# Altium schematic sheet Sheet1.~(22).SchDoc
size A; SheetNumber: 1; SheetTotal: 1
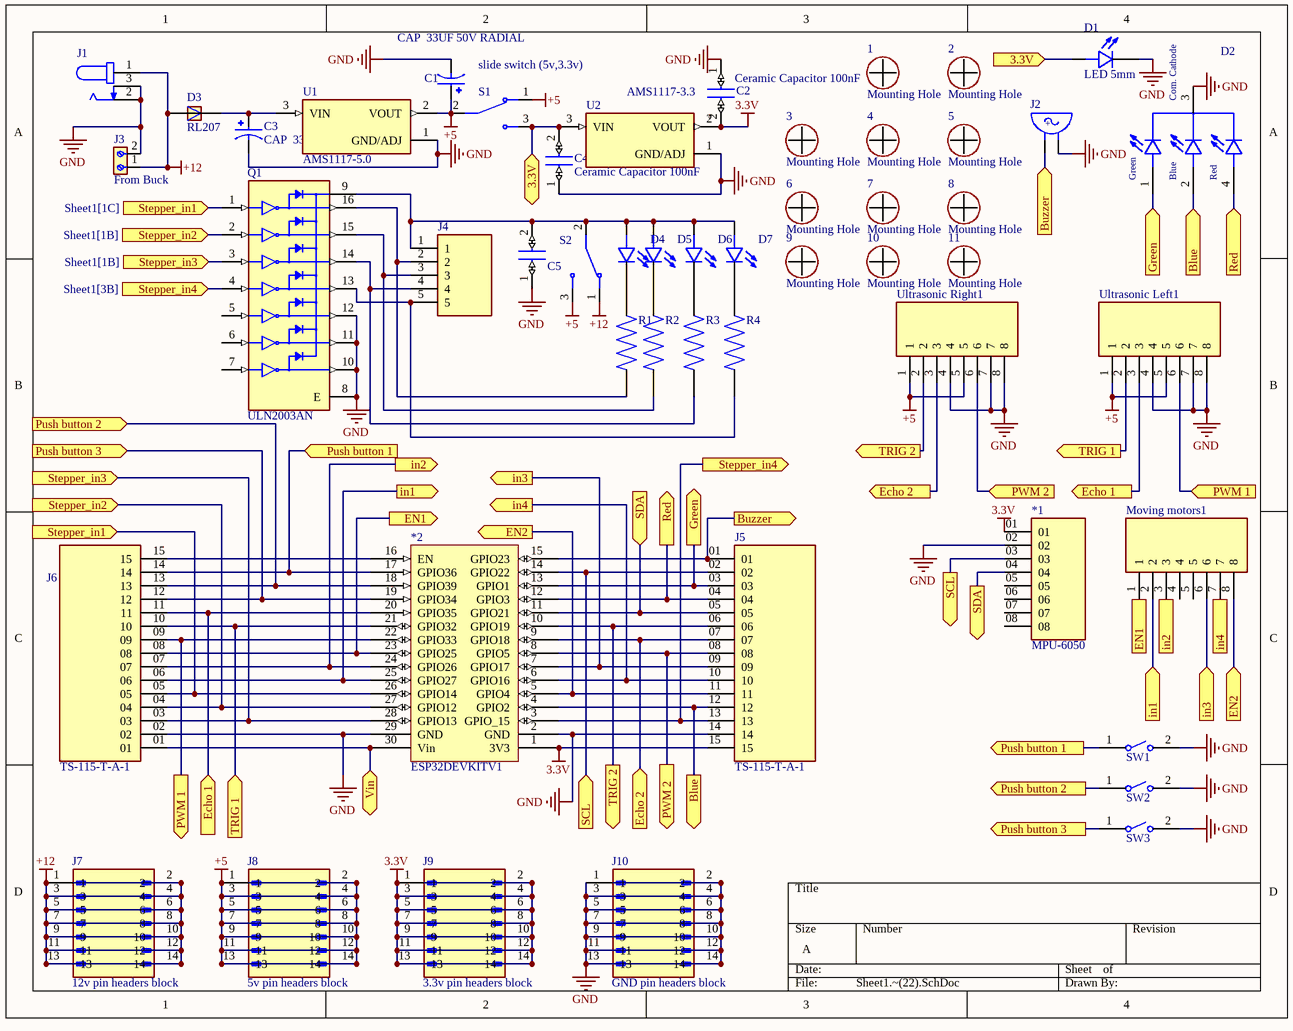
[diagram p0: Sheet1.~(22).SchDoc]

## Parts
1  Mounting Hole  [PCBComponent_1]
2  Mounting Hole  [PCBComponent_1]
3  Mounting Hole  [PCBComponent_1]
4  Mounting Hole  [PCBComponent_1]
5  Mounting Hole  [PCBComponent_1]
6  Mounting Hole  [PCBComponent_1]
7  Mounting Hole  [PCBComponent_1]
8  Mounting Hole  [PCBComponent_1]
9  Mounting Hole  [PCBComponent_1]
10  Mounting Hole  [PCBComponent_1]
11  Mounting Hole  [PCBComponent_1]
*1  MPU-6050  [MPU-6050]
*2  ESP32DEVKITV1  [ESP32DEVKITV1]
C1  CAP  33UF 50V RADIAL  [CAP  33UF 50V RADIAL]
C2  Ceramic Capacitor 100nF  [C320C]
C3  CAP  33UF 50V RADIAL  [CAP  33UF 50V RADIAL]
C4  Ceramic Capacitor 100nF  [C320C]
C5  Ceramic Capacitor 100nF  [C320C]  (value not drawn)
D1  LED 5mm  [LED 5mm]
D2  common cathode  [LED RGB 5mm]  (value not drawn)
D3  RL207  [DIOAD1300W80L670D310]
D4  LED 5mm  [LED 5mm]  (value not drawn)
D5  LED 5mm  [LED 5mm]  (value not drawn)
D6  LED 5mm  [LED 5mm]  (value not drawn)
D7  LED 5mm  [LED 5mm]  (value not drawn)
J1  DC Power Jack Female Socket  [DC Power Jack Female Socket]  (value not drawn)
J2  WST-1205S  [WST-1205S]  (value not drawn)
J3  From Buck  [691213510002]
J4  Pin hreader 5 pins  [Pin hreader 5 pins]  (value not drawn)
J5  TS-115-T-A-1  [SAMTEC_TS-115-T-A-1]
J6  TS-115-T-A-1  [SAMTEC_TS-115-T-A-1]
J7  12v pin headers block  [AMPHENOL_52601-S14-4LF]
J8  5v pin headers block  [AMPHENOL_52601-S14-4LF]
J9  3.3v pin headers block  [AMPHENOL_52601-S14-4LF]
J10  GND pin headers block  [AMPHENOL_52601-S14-4LF]
Moving_motors1  Pin header female block 8 pin  [Pin header female block 8 pin]  (value not drawn)
Q1  ULN2003AN  [DIP794W45P254L1969H508Q16]
R1  Resistor  [RESAD700W45L350D185]  (value not drawn)
R2  Resistor  [RESAD700W45L350D185]  (value not drawn)
R3  Resistor  [RESAD700W45L350D185]  (value not drawn)
R4  Resistor  [RESAD700W45L350D185]  (value not drawn)
S1  slide switch (5v,3.3v)  [Slide switch]
S2  Slide switch  [Slide switch]  (value not drawn)
SW1  FSM8JRT  [TE_FSM8JRT]  (value not drawn)
SW2  FSM8JRT  [TE_FSM8JRT]  (value not drawn)
SW3  FSM8JRT  [TE_FSM8JRT]  (value not drawn)
U1  AMS1117-5.0  [SOT229P700X180-4N]
U2  AMS1117-3.3  [SOT229P700X180-4N]
Ultrasonic_Left1  Pin header female block 8 pin  [Pin header female block 8 pin]  (value not drawn)
Ultrasonic_Right1  Pin header female block 8 pin  [Pin header female block 8 pin]  (value not drawn)

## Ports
3.3V (bidir, see Sheet1[4A]), 3.3V (in, see Sheet1[2A]), Blue (in, see Sheet1[3D]), Blue (out, see Sheet1[4B]), Buzzer (in, see Sheet1[3C]), Buzzer (out, see Sheet1[4A]), Echo 1 (in, see Sheet1[4B]), Echo 1 (out, see Sheet1[1D]), Echo 2 (in, see Sheet1[3B]), Echo 2 (out, see Sheet1[2D]), EN1 (in, see Sheet1[2C]), EN1 (out, see Sheet1[4C]), EN2 (in, see Sheet1[2C]), EN2 (out, see Sheet1[4C]), Green (in, see Sheet1[3C]), Green (out, see Sheet1[4B]), in1 (in, see Sheet1[2B]), in1 (out, see Sheet1[4C]), in2 (in, see Sheet1[2B]), in2 (out, see Sheet1[4C]), in3 (in, see Sheet1[2B]), in3 (out, see Sheet1[4C]), in4 (in, see Sheet1[2B]), in4 (out, see Sheet1[4C]), Push button 1 (in, see Sheet1[4C]), Push button 1 (out, see Sheet1[1B]), Push button 2 (in, see Sheet1[4D]), Push button 2 (out, see Sheet1[1B]), Push button 3 (in, see Sheet1[4D]), Push button 3 (out, see Sheet1[1B]), PWM 1 (in, see Sheet1[1D]), PWM 1 (out, see Sheet1[4B]), PWM 2 (in, see Sheet1[3D]), PWM 2 (out, see Sheet1[4B]), Red (in, see Sheet1[3C]), Red (out, see Sheet1[4B]), SCL (in, see Sheet1[3C]), SCL (out, see Sheet1[2D]), SDA (in, see Sheet1[4C]), SDA (out, see Sheet1[2C]), Stepper_in1 (in, see Sheet1[1A]), Stepper_in1 (in, see Sheet1[1C]), Stepper_in2 (in, see Sheet1[1A]), Stepper_in2 (in, see Sheet1[1B]), Stepper_in3 (in, see Sheet1[1B]), Stepper_in4 (in, see Sheet1[3B]), Stepper_in4 (out, see Sheet1[1B]), TRIG 1 (in, see Sheet1[4B]), TRIG 1 (out, see Sheet1[1D]), TRIG 2 (out, see Sheet1[2D]), TRIG 2 (out, see Sheet1[3B]), Vin (bidir)

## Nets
3.3V: *1.01 *2.1(3V3) C2.2 J5.15 J9.1 J9.2 J9.3 J9.4 J9.5 J9.6 J9.7 J9.8 J9.9 J9.10 J9.11 J9.12 J9.13 J9.14 U2.2(VOUT)
+5: C1.P J8.1 J8.2 J8.3 J8.4 J8.5 J8.6 J8.7 J8.8 J8.9 J8.10 J8.11 J8.12 J8.13 J8.14 S1.1 S1.2 S2.3 U1.2(VOUT) Ultrasonic_Left1.1 Ultrasonic_Left1.5 Ultrasonic_Right1.1 Ultrasonic_Right1.5
+12: D3.A J1.1 J3.1 J7.1 J7.2 J7.3 J7.4 J7.5 J7.6 J7.7 J7.8 J7.9 J7.10 J7.11 J7.12 J7.13 J7.14 S2.1
GND: *1.02 *2.2(GND) *2.29(GND) C1.N C2.1 C3.N C4.1 C5.1 D1.C D2.3(Com._Cathode) J1.2 J1.3 J2.NEG J3.2 J5.14 J6.02 J10.1 J10.2 J10.3 J10.4 J10.5 J10.6 J10.7 J10.8 J10.9 J10.10 J10.11 J10.12 J10.13 J10.14 Q1.8(E) Q1.10(7C) Q1.11(6C) Q1.12(5C) SW1.2 SW2.2 SW3.2 U1.1(GND/ADJ) U2.1(GND/ADJ) Ultrasonic_Left1.4 Ultrasonic_Left1.7 Ultrasonic_Left1.8 Ultrasonic_Right1.4 Ultrasonic_Right1.7 Ultrasonic_Right1.8
3.3V: C4.2 D1.A S1.3 U2.3(VIN) ; port 3.3V  [a separate net that carries the same name]
Blue: *2.4(GPIO2) D2.2(BLUE) J5.12 ; port Blue
Buzzer: *2.15(GPIO23) J2.POS J5.01 ; port Buzzer
Echo 1: *2.20(GPIO35) J6.11 Ultrasonic_Left1.3 ; port Echo 1
Echo 2: *2.9(GPIO18) J5.07 Ultrasonic_Right1.3 ; port Echo 2
EN1: *2.23(GPIO25) J6.08 Moving_motors1.1 ; port EN1
EN2: *2.5(GPIO4) J5.11 Moving_motors1.8 ; port EN2
Green: *2.13(GPIO1) D2.1(Green) J5.03 ; port Green
in1: *2.25(GPIO27) J6.06 Moving_motors1.2 ; port in1
in2: *2.24(GPIO26) J6.07 Moving_motors1.3 ; port in2
in3: *2.7(GPIO17) J5.09 Moving_motors1.6 ; port in3
in4: *2.6(GPIO16) J5.10 Moving_motors1.7 ; port in4
Push button 1: *2.17(GPIO36) J6.14 SW1.1 ; port Push button 1
Push button 2: *2.18(GPIO39) J6.13 SW2.1 ; port Push button 2
Push button 3: *2.19(GPIO34) J6.12 SW3.1 ; port Push button 3
PWM 1: *2.22(GPIO33) J6.09 Ultrasonic_Left1.6 ; port PWM 1
PWM 2: *2.8(GPIO5) J5.08 Ultrasonic_Right1.6 ; port PWM 2
Red: *2.12(GPIO3) D2.4(Red) J5.04 ; port Red
SCL: *1.03 *2.14(GPIO22) J5.02 ; port SCL
SDA: *1.04 *2.11(GPIO21) J5.05 ; port SDA
Stepper_in1: *2.26(GPIO14) J6.05 Q1.1(1B) ; port Stepper_in1
Stepper_in2: *2.27(GPIO12) J6.04 Q1.2(2B) ; port Stepper_in2
Stepper_in3: *2.28(GPIO13) J6.03 Q1.3(3B) ; port Stepper_in3
Stepper_in4: *2.3(GPIO_15) J5.13 Q1.4(4B) ; port Stepper_in4
TRIG 1: *2.21(GPIO32) J6.10 Ultrasonic_Left1.2 ; port TRIG 1
TRIG 2: *2.10(GPIO19) J5.06 Ultrasonic_Right1.2 ; port TRIG 2
Vin: *2.30(Vin) J6.01 ; port Vin
Net*2_16: *2.16(EN) J6.15
NetC3_P: C3.P D3.C U1.3(VIN)
NetC5_2: C5.2 D4.A D5.A D6.A D7.A J4.1 Q1.9(COM) S2.2
NetD4_C: D4.C R1.1
NetD5_C: D5.C R2.1
NetD6_C: D6.C R3.1
NetD7_C: D7.C R4.1
NetJ4_2: J4.2 Q1.16(1C) R1.2
NetJ4_3: J4.3 Q1.15(2C) R2.2
NetJ4_4: J4.4 Q1.14(3C) R3.2
NetJ4_5: J4.5 Q1.13(4C) R4.2

Not connected (* = marked no-connect by the designer): *1 05 06 07 08; Moving_motors1 4 5; Q1 5(5B) 6(6B) 7(7B)

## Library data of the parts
C1 C3 = CAP  33UF 50V RADIAL: NHG-A; MF: {'manufacturer': u'Panasonic'}; MP: ECA1HHG330I
C2 C4 C5 = Ceramic Capacitor 100nF: 0.1ÂµF Â±20% 50V Ceramic Capacitor Z5U Radial; MF: KEMET; MP: C320C104M5U5TA
D1 D4-D7 = LED 5mm: Red 623nm LED Indication - Discrete 1.9V Radial; MF: {'manufacturer': u'Wurth Elektronik'}; MP: 151054RS03000
D2 = LED RGB 5mm: MF: {'manufacturer': u'Kingbright'}; MP: WP154A4SUREQBFZGC
D3 = RL207: Semiconductors and Actives, Power Diodes, Discretes (diodes, transistors, thyristors ...), Diodes; MF: {'manufacturer': u'Diodes Inc.'}
J1 = DC Power Jack Female Socket: 2.0 mm Center Pin, 2.5 A, Right Angle, Through Hole, Dc Power Jack Connector; MF: {'manufacturer': u'CUI Devices'}; MP: PJ-002A
J2 = WST-1205S: BUZZER 2.3KHZ 4-6VDC; MF: {'manufacturer': u'Soberton Inc.'}
J3 = Terminal Block: 2 Position Wire to Board Terminal Block Horizontal with Board 0.200 (5.08mm) Through Hole; MF: Wurth Electronics
J4 = Pin hreader 5 pins: MF: {'manufacturer': u'TE Connectivity'}; MP: 2355181-5
J5 J6 = TS-115-T-A-1: MF: {'manufacturer': u'Samtec'}
J7-J10 = 52601-S14-4LF: MF: {'manufacturer': u'Amphenol ICC (FCI)'}
Moving_motors1 Ultrasonic_Left1 Ultrasonic_Right1 = Pin header female block 8 pin: MF: {'manufacturer': u'TE Connectivity'}; MP: 5-534998-4
Q1 = ULN2003AN: MF: {'manufacturer': u'Texas Instruments'}
R1-R4 = Resistor: CFR16 5% 10K; MF: {'manufacturer': u'TE Connectivity'}; MP: 2-1623927-3
S1 S2 = Slide switch: MF: {'manufacturer': u'E-Switch'}; MP: EG1206
SW1-SW3 = FSM8JRT: Tactile Switches PUSHBUTTON SWITCH TACT; MF: {'manufacturer': u'TE Connectivity'}
U1 = AMS1117-5.0: MF: {'manufacturer': u'Advanced Monolithic Systems'}
U2 = AMS1117-3.3: MF: {'manufacturer': u'Advanced Monolithic Systems'}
